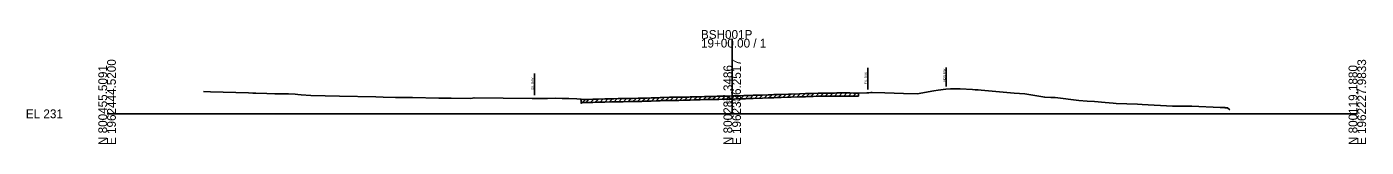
# Model space of a CAD drawing. Extents: x -26 to 1403, y -10 to 19587.
# Drawn here: x -25.7 to 402.8, y 2990.3 to 3026.9 of the extents above; entities that cross this region are included whole.
import ezdxf

# ---------------------------------------------------------------- set-up
doc = ezdxf.new("R2010")
doc.units = 0
for name, color, linetype in [('Default', 7, 'Continuous'), ('RD_GPK_XS_Cell', 7, 'Continuous'), ('RD_XS_ExGround', 7, 'Continuous'), ('RD_XS_ExPaveRet', 7, 'Continuous'), ('RD_XS_ExRW', 7, 'Continuous'), ('RD_XS_NewRW', 7, 'Continuous'), ('RD_XS_TX_Elev_EX', 7, 'Continuous')]:
    doc.layers.add(name, color=color, linetype=linetype)

msp = doc.modelspace()

# ---------------------------------------------------------------- linework, layer by layer
at = {"layer": 'RD_GPK_XS_Cell'}
for p, q in [((200, 3000), (200, 3024.02)), ((0, 3000), (200, 3000)), ((200, 3000), (400, 3000))]:
    msp.add_line(p, q, dxfattribs=at)
at = {"layer": 'RD_XS_ExGround'}
msp.add_lwpolyline([(30.81, 3007.11), (33.11, 3007), (45.28, 3006.67), (46.59, 3006.63), (47.05, 3006.62), (47.6, 3006.6), (51.12, 3006.52), (53.65, 3006.45), (58.03, 3006.36), (60.14, 3006.24), (61.03, 3006.18), (62.04, 3006.11), (65.15, 3005.9), (74.38, 3005.68), (85.97, 3005.4), (88.31, 3005.34), (92.29, 3005.27), (93.36, 3005.26), (95.13, 3005.23), (97.71, 3005.2), (106.11, 3005.04), (107.47, 3005.05), (109.16, 3005.05), (110.1, 3005.04), (116.38, 3004.94), (117.41, 3005.17), (136, 3004.93), (140.91, 3004.95), (143.37, 3004.96), (145.55, 3004.94), (147.74, 3004.89), (150.25, 3004.79), (151.5, 3004.72), (151.7, 3004.28), (151.86, 3004.64), (152.44, 3004.63), (153.42, 3004.62), (154, 3004.63), (155.45, 3004.67), (156.2, 3004.71), (157.23, 3004.72), (159.27, 3004.77), (161.37, 3004.83), (162.15, 3004.85), (163.47, 3004.86), (165.08, 3004.88), (166.7, 3004.9), (168.1, 3004.91), (169.91, 3004.96), (171.04, 3004.99), (171.69, 3005.01), (172.76, 3005.05), (174.02, 3005.09), (176.25, 3005.17), (176.99, 3005.2), (177.39, 3005.21), (179.94, 3005.28), (181.96, 3005.3), (182.89, 3005.31), (184.31, 3005.35), (186.17, 3005.38), (186.58, 3005.39), (187.92, 3005.43), (188.84, 3005.46), (189.77, 3005.49), (191.16, 3005.53), (191.81, 3005.54), (193.01, 3005.56), (194.78, 3005.59), (195.17, 3005.6), (195.75, 3005.61), (196.99, 3005.64), (197.77, 3005.66), (198.85, 3005.69), (200, 3005.72), (200.77, 3005.74), (201.39, 3005.76), (203.74, 3005.83), (204.25, 3005.84), (205.07, 3005.86), (206.08, 3005.9), (206.72, 3005.92), (209.69, 3006.01), (211.49, 3006.08), (212.67, 3006.12), (213.3, 3006.15), (214.3, 3006.18), (215.63, 3006.23), (218, 3006.3), (218.59, 3006.31), (218.91, 3006.32), (221.55, 3006.4), (223.48, 3006.46), (224.52, 3006.5), (225.92, 3006.55), (227.5, 3006.62), (228.2, 3006.63), (228.62, 3006.63), (230.01, 3006.64), (230.69, 3006.65), (231.37, 3006.65), (232.75, 3006.66), (233.45, 3006.67), (236.1, 3006.7), (236.5, 3006.7), (237.66, 3006.68), (238.77, 3006.66), (239.91, 3006.65), (240.54, 3006.63), (243.12, 3006.74), (243.72, 3006.77), (244.38, 3006.79), (244.74, 3006.8), (248.83, 3006.73), (254.78, 3006.5), (259.16, 3006.37), (264.47, 3007.32), (265.87, 3007.55), (268.34, 3007.92), (269.83, 3007.99), (271.88, 3008.01), (272.94, 3007.97), (276.91, 3007.75), (277.69, 3007.68), (278.66, 3007.66), (279.62, 3007.53), (290.25, 3006.62), (293.59, 3006.42), (299.98, 3005.33), (301.95, 3005.22), (303.31, 3005.2), (310.92, 3004.23), (313.56, 3004.08), (315.89, 3003.9), (319.31, 3003.59), (321.91, 3003.43), (322.81, 3003.33), (329.64, 3003.08), (331.21, 3003), (340.86, 3002.49), (347.07, 3002.4), (356.15, 3002.07), (356.51, 3002.06), (357.3, 3002.04), (357.62, 3002.04), (357.62, 3001.91), (358.43, 3001.89), (359.21, 3001.29)], dxfattribs=at)
at = {"layer": 'RD_XS_ExPaveRet'}
for p, q in [((151.7, 3003.28), (153.05, 3004.63)), ((151.7, 3003.28), (151.7, 3004.28)), ((153.2, 3003.62), (154.22, 3004.64)), ((154.7, 3003.65), (155.74, 3004.68)), ((156.2, 3003.71), (157.22, 3004.72)), ((157.7, 3003.73), (158.73, 3004.76)), ((159.2, 3003.77), (160.23, 3004.8)), ((160.7, 3003.81), (161.73, 3004.84)), ((162.2, 3003.85), (163.21, 3004.86)), ((163.7, 3003.86), (164.72, 3004.88)), ((165.2, 3003.88), (166.22, 3004.89)), ((166.7, 3003.9), (167.72, 3004.91)), ((168.2, 3003.92), (169.23, 3004.94)), ((169.7, 3003.96), (170.73, 3004.99)), ((171.04, 3003.99), (171.69, 3004.01)), ((171.2, 3004), (172.24, 3005.03)), ((171.69, 3004.01), (172.76, 3004.05)), ((172.7, 3004.04), (173.74, 3005.08)), ((172.76, 3004.05), (174.02, 3004.09)), ((174.02, 3004.09), (176.25, 3004.17)), ((174.2, 3004.09), (175.24, 3005.13)), ((175.7, 3004.15), (176.74, 3005.19)), ((176.25, 3004.17), (176.99, 3004.2)), ((176.99, 3004.2), (177.39, 3004.21)), ((177.2, 3004.21), (178.23, 3005.24)), ((177.39, 3004.21), (179.94, 3004.28)), ((178.7, 3004.25), (179.73, 3005.27)), ((179.94, 3004.28), (181.96, 3004.3)), ((180.2, 3004.28), (181.21, 3005.29)), ((181.7, 3004.29), (182.72, 3005.31)), ((181.96, 3004.3), (182.89, 3004.31)), ((182.89, 3004.31), (184.31, 3004.35)), ((183.2, 3004.32), (184.23, 3005.34)), ((184.31, 3004.35), (186.17, 3004.38)), ((184.7, 3004.35), (185.72, 3005.37)), ((186.17, 3004.38), (186.58, 3004.39)), ((186.2, 3004.38), (187.23, 3005.41)), ((186.58, 3004.39), (187.92, 3004.43)), ((187.7, 3004.43), (188.74, 3005.46)), ((187.92, 3004.43), (188.84, 3004.46)), ((188.84, 3004.46), (189.77, 3004.49)), ((189.2, 3004.47), (190.23, 3005.5)), ((189.77, 3004.49), (191.16, 3004.53)), ((190.7, 3004.51), (191.73, 3005.54)), ((191.16, 3004.53), (191.81, 3004.54)), ((191.81, 3004.54), (193.01, 3004.56)), ((192.2, 3004.55), (193.22, 3005.57)), ((193.01, 3004.56), (194.78, 3004.59)), ((193.7, 3004.57), (194.72, 3005.59)), ((194.78, 3004.59), (195.17, 3004.6)), ((195.17, 3004.6), (195.75, 3004.61)), ((195.2, 3004.6), (196.23, 3005.62)), ((195.75, 3004.61), (196.99, 3004.64)), ((196.7, 3004.63), (197.73, 3005.66)), ((196.99, 3004.64), (197.77, 3004.66)), ((197.77, 3004.66), (198.85, 3004.69)), ((198.2, 3004.67), (199.23, 3005.7)), ((198.85, 3004.69), (200, 3004.72)), ((199.7, 3004.71), (200.73, 3005.74)), ((200, 3004.72), (200.77, 3004.74)), ((200.77, 3004.74), (201.39, 3004.76)), ((201.2, 3004.76), (202.23, 3005.78)), ((201.39, 3004.76), (203.74, 3004.83)), ((202.7, 3004.8), (203.73, 3005.83)), ((203.74, 3004.83), (204.25, 3004.84)), ((204.2, 3004.84), (205.24, 3005.87)), ((204.25, 3004.84), (205.07, 3004.86)), ((205.07, 3004.86), (206.08, 3004.9)), ((205.7, 3004.88), (206.74, 3005.92)), ((206.08, 3004.9), (206.72, 3004.92)), ((206.72, 3004.92), (209.69, 3005.01)), ((207.2, 3004.93), (208.24, 3005.96)), ((208.7, 3004.98), (209.74, 3006.01)), ((209.69, 3005.01), (211.49, 3005.08)), ((210.2, 3005.03), (211.25, 3006.07)), ((211.49, 3005.08), (212.67, 3005.12)), ((211.7, 3005.09), (212.74, 3006.13)), ((212.67, 3005.12), (213.3, 3005.15)), ((213.2, 3005.14), (214.24, 3006.18)), ((213.3, 3005.15), (214.3, 3005.18)), ((214.3, 3005.18), (215.63, 3005.23)), ((214.7, 3005.2), (215.74, 3006.23)), ((215.63, 3005.23), (218, 3005.3)), ((216.2, 3005.25), (217.23, 3006.28)), ((217.7, 3005.29), (218.73, 3006.32)), ((218, 3005.3), (218.59, 3005.31)), ((218.59, 3005.31), (218.91, 3005.32)), ((218.91, 3005.32), (221.55, 3005.4)), ((219.2, 3005.33), (220.23, 3006.36)), ((220.7, 3005.37), (221.73, 3006.4)), ((221.55, 3005.4), (223.48, 3005.46)), ((222.2, 3005.42), (223.24, 3006.45)), ((223.48, 3005.46), (224.52, 3005.5)), ((223.7, 3005.47), (224.74, 3006.51)), ((224.52, 3005.5), (225.92, 3005.55)), ((225.2, 3005.53), (226.25, 3006.57)), ((225.92, 3005.55), (227.5, 3005.62)), ((226.7, 3005.59), (227.74, 3006.62)), ((227.5, 3005.62), (228.2, 3005.63)), ((228.2, 3005.63), (229.21, 3006.63)), ((228.2, 3005.63), (228.62, 3005.63)), ((228.62, 3005.63), (230.01, 3005.64)), ((229.7, 3005.64), (230.71, 3006.65)), ((230.01, 3005.64), (230.69, 3005.65)), ((230.69, 3005.65), (231.37, 3005.65)), ((231.2, 3005.65), (232.21, 3006.66)), ((231.37, 3005.65), (232.75, 3005.66)), ((232.7, 3005.66), (233.72, 3006.68)), ((232.75, 3005.66), (233.45, 3005.67)), ((233.45, 3005.67), (236.1, 3005.7)), ((234.2, 3005.68), (235.21, 3006.69)), ((235.7, 3005.7), (236.7, 3006.7)), ((236.1, 3005.7), (236.5, 3005.7)), ((236.5, 3005.7), (237.66, 3005.68)), ((237.2, 3005.69), (238.19, 3006.67)), ((237.66, 3005.68), (238.77, 3005.66)), ((238.7, 3005.67), (239.69, 3006.65)), ((238.77, 3005.66), (239.91, 3005.65)), ((239.91, 3005.65), (240.42, 3005.64)), ((240.42, 3006.64), (240.42, 3005.64)), ((151.7, 3003.28), (151.86, 3003.64)), ((151.86, 3003.64), (152.44, 3003.63)), ((152.44, 3003.63), (153.42, 3003.62)), ((153.42, 3003.62), (154, 3003.63)), ((154, 3003.63), (155.45, 3003.67)), ((155.45, 3003.67), (156.2, 3003.71)), ((156.2, 3003.71), (157.23, 3003.72)), ((157.23, 3003.72), (159.27, 3003.77)), ((159.27, 3003.77), (161.37, 3003.83)), ((161.37, 3003.83), (162.15, 3003.85)), ((162.15, 3003.85), (163.47, 3003.86)), ((163.47, 3003.86), (165.08, 3003.88)), ((165.08, 3003.88), (166.7, 3003.9)), ((166.7, 3003.9), (168.1, 3003.91)), ((168.1, 3003.91), (169.91, 3003.96)), ((169.91, 3003.96), (171.04, 3003.99))]:
    msp.add_line(p, q, dxfattribs=at)
at = {"layer": 'RD_XS_ExRW'}
for p, q in [((136.75, 3005.93), (136.75, 3012.93)), ((243.41, 3007.75), (243.41, 3014.75))]:
    msp.add_line(p, q, dxfattribs=at)
at = {"layer": 'RD_XS_NewRW'}
msp.add_line((268.46, 3014.79), (268.46, 3008.79), dxfattribs=at)

# ---------------------------------------------------------------- texts
at = {"layer": 'Default'}
msp.add_text('-', height=0.0001, dxfattribs=at).set_placement((0, 3000))
at = {"layer": 'RD_GPK_XS_Cell'}
for s, p in [('BSH001P', (190, 3024.02)), ('19+00.00 / 1', (190, 3021.22)), ('EL 231', (-26, 2998.6))]:
    msp.add_text(s, height=2.8, dxfattribs=at).set_placement(p)
for s, p in [('E 1962444.5200', (2.8, 2990)), ('E 1962336.2517', (202.8, 2990)), ('E 1962227.9833', (402.8, 2990)), ('N 800455.5091', (0, 2990)), ('N 800287.3486', (200, 2990)), ('N 800119.1880', (400, 2990))]:
    msp.add_text(s, height=2.8, rotation=90, dxfattribs=at).set_placement(p)
at = {"layer": 'RD_XS_ExRW'}
for p in [(243.16, 3009.43), (136.5, 3007.6)]:
    msp.add_text('EX. R/W ', height=0.75, rotation=90, dxfattribs=at).set_placement(p)
at = {"layer": 'RD_XS_NewRW'}
msp.add_text('NEW R/W ', height=0.65, rotation=90, dxfattribs=at).set_placement((268.2, 3010.35))
at = {"layer": 'RD_XS_TX_Elev_EX'}
msp.add_text('236.72', height=1, dxfattribs=at).set_placement((197.96, 3003.22))

doc.saveas('drawing.dxf')
